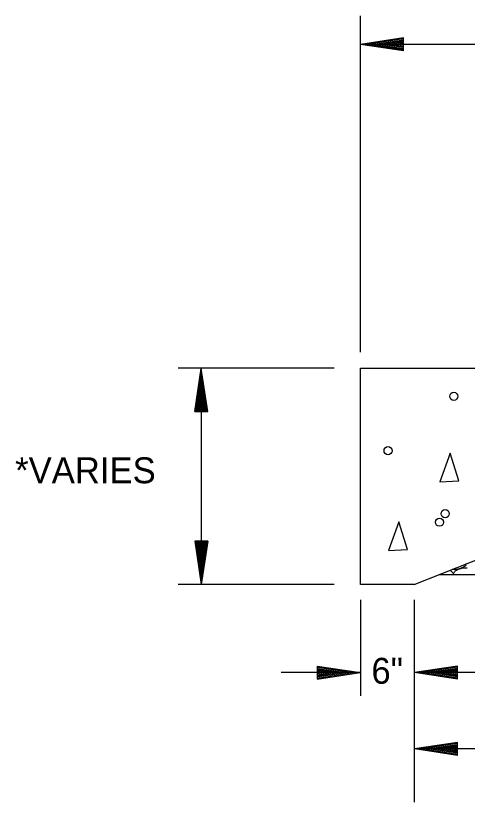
# Model space of a CAD drawing. Extents: x 1955771 to 1955918, y 566326 to 566544.
# Drawn here: x 1955782.9 to 1955793.36, y 566390.76 to 566408.95 of the extents above; entities that cross this region are included whole.
import ezdxf

# ---------------------------------------------------------------- set-up
doc = ezdxf.new("R2010")
doc.units = 0
doc.layers.add('Default', color=7, linetype='Continuous')

msp = doc.modelspace()

# ---------------------------------------------------------------- linework, layer by layer
at = {"layer": 'Default'}
for p, q in [((1955790.884, 566401.168), (1955790.884, 566408.948)), ((1955791.885, 566408.436), (1955790.885, 566408.286)), ((1955791.885, 566408.411), (1955791.052, 566408.286)), ((1955791.885, 566408.136), (1955791.885, 566408.436)), ((1955790.884, 566408.287), (1955840.88, 566408.287)), ((1955791.885, 566408.136), (1955790.885, 566408.286)), ((1955791.885, 566408.161), (1955791.052, 566408.286)), ((1955791.885, 566408.386), (1955791.222, 566408.286)), ((1955791.885, 566408.186), (1955791.222, 566408.286)), ((1955791.885, 566408.361), (1955791.39, 566408.286)), ((1955791.885, 566408.211), (1955791.39, 566408.286)), ((1955791.885, 566408.336), (1955791.56, 566408.286)), ((1955791.885, 566408.239), (1955791.56, 566408.286)), ((1955791.885, 566408.311), (1955791.727, 566408.286)), ((1955791.885, 566408.264), (1955791.727, 566408.286)), ((1955790.28, 566400.793), (1955786.667, 566400.793)), ((1955787.05, 566399.792), (1955787.2, 566400.792)), ((1955787.35, 566399.792), (1955787.2, 566400.792)), ((1955787.201, 566400.793), (1955787.201, 566395.793)), ((1955790.884, 566400.793), (1955882.128, 566400.793)), ((1955790.884, 566395.793), (1955790.884, 566400.793)), ((1955787.075, 566399.792), (1955787.2, 566400.627)), ((1955787.325, 566399.792), (1955787.2, 566400.627)), ((1955787.103, 566399.792), (1955787.2, 566400.454)), ((1955787.3, 566399.792), (1955787.2, 566400.454)), ((1955787.128, 566399.792), (1955787.2, 566400.287)), ((1955787.275, 566399.792), (1955787.2, 566400.287)), ((1955787.153, 566399.792), (1955787.2, 566400.117)), ((1955787.25, 566399.792), (1955787.2, 566400.117)), ((1955787.178, 566399.792), (1955787.2, 566399.952)), ((1955787.225, 566399.792), (1955787.2, 566399.952)), ((1955787.05, 566399.792), (1955787.35, 566399.792)), ((1955792.133, 566395.793), (1955797.133, 566397.772)), ((1955787.05, 566396.792), (1955787.2, 566395.792)), ((1955787.35, 566396.792), (1955787.05, 566396.792)), ((1955787.075, 566396.792), (1955787.2, 566395.959)), ((1955787.103, 566396.792), (1955787.2, 566396.132)), ((1955787.128, 566396.792), (1955787.2, 566396.299)), ((1955787.153, 566396.792), (1955787.2, 566396.467)), ((1955787.178, 566396.792), (1955787.2, 566396.634)), ((1955787.35, 566396.792), (1955787.2, 566395.792)), ((1955787.25, 566396.792), (1955787.2, 566396.467)), ((1955787.3, 566396.792), (1955787.2, 566396.132)), ((1955787.325, 566396.792), (1955787.2, 566395.959)), ((1955787.275, 566396.792), (1955787.2, 566396.299)), ((1955787.225, 566396.792), (1955787.2, 566396.634)), ((1955793.352, 566396.182), (1955793.36, 566396.182)), ((1955792.712, 566396.022), (1955837.131, 566396.022)), ((1955790.28, 566395.793), (1955786.667, 566395.793)), ((1955792.133, 566395.793), (1955790.884, 566395.793)), ((1955790.884, 566395.44), (1955790.884, 566393.221)), ((1955792.133, 566395.44), (1955792.133, 566390.756)), ((1955789.885, 566393.904), (1955790.885, 566393.754)), ((1955789.885, 566393.904), (1955789.885, 566393.604)), ((1955789.885, 566393.879), (1955790.717, 566393.754)), ((1955793.135, 566393.904), (1955792.135, 566393.754)), ((1955793.135, 566393.879), (1955792.302, 566393.754)), ((1955793.135, 566393.604), (1955793.135, 566393.904)), ((1955790.884, 566393.755), (1955789.048, 566393.755)), ((1955789.885, 566393.854), (1955790.545, 566393.754)), ((1955789.885, 566393.829), (1955790.38, 566393.754)), ((1955789.885, 566393.804), (1955790.21, 566393.754)), ((1955789.885, 566393.779), (1955790.043, 566393.754)), ((1955789.885, 566393.604), (1955790.885, 566393.754)), ((1955789.885, 566393.707), (1955790.21, 566393.754)), ((1955789.885, 566393.654), (1955790.545, 566393.754)), ((1955789.885, 566393.629), (1955790.717, 566393.754)), ((1955789.885, 566393.679), (1955790.38, 566393.754)), ((1955789.885, 566393.732), (1955790.043, 566393.754)), ((1955794.099, 566393.755), (1955792.133, 566393.755)), ((1955793.135, 566393.604), (1955792.135, 566393.754)), ((1955793.135, 566393.629), (1955792.302, 566393.754)), ((1955793.135, 566393.854), (1955792.472, 566393.754)), ((1955793.135, 566393.654), (1955792.472, 566393.754)), ((1955793.135, 566393.829), (1955792.64, 566393.754)), ((1955793.135, 566393.679), (1955792.64, 566393.754)), ((1955793.135, 566393.804), (1955792.81, 566393.754)), ((1955793.135, 566393.707), (1955792.81, 566393.754)), ((1955793.135, 566393.779), (1955792.977, 566393.754)), ((1955793.135, 566393.732), (1955792.977, 566393.754)), ((1955793.135, 566392.14), (1955792.135, 566391.99)), ((1955793.135, 566392.115), (1955792.302, 566391.99)), ((1955793.135, 566392.087), (1955792.472, 566391.99)), ((1955793.135, 566392.062), (1955792.64, 566391.99)), ((1955793.135, 566391.84), (1955793.135, 566392.14)), ((1955797.133, 566391.989), (1955792.133, 566391.989)), ((1955793.135, 566391.84), (1955792.135, 566391.99)), ((1955793.135, 566391.865), (1955792.302, 566391.99)), ((1955793.135, 566391.89), (1955792.472, 566391.99)), ((1955793.135, 566391.915), (1955792.64, 566391.99)), ((1955793.135, 566392.037), (1955792.81, 566391.99)), ((1955793.135, 566391.94), (1955792.81, 566391.99)), ((1955793.135, 566392.012), (1955792.977, 566391.99)), ((1955793.135, 566391.965), (1955792.977, 566391.99))]:
    msp.add_line(p, q, dxfattribs=at)
for points in [[(1955792.967, 566398.834), (1955792.725, 566398.169), (1955793.165, 566398.187), (1955792.967, 566398.834)], [(1955791.777, 566397.244), (1955791.535, 566396.579), (1955791.975, 566396.599), (1955791.777, 566397.244)]]:
    msp.add_lwpolyline(points, dxfattribs=at)
for centre in [(1955793.047, 566400.146), (1955791.525, 566398.888), (1955792.848, 566397.431), (1955792.716, 566397.233)]:
    msp.add_circle(centre, 0.0937, dxfattribs=at)
for points in [[(1955793.337, 566396.27), (1955793.31, 566396.227), (1955793.272, 566396.197), (1955793.195, 566396.162), (1955793.087, 566396.14), (1955793.032, 566396.14), (1955793.013, 566396.141)], [(1955792.963, 566396.122), (1955793.022, 566396.062), (1955793.032, 566396.025), (1955793.032, 566396.022)], [(1955793.04, 566396.022), (1955793.04, 566396.025), (1955793.06, 566396.085), (1955793.11, 566396.125), (1955793.16, 566396.147), (1955793.235, 566396.17), (1955793.282, 566396.18), (1955793.352, 566396.182)]]:
    msp.add_spline(points, degree=3, dxfattribs=at)

# ---------------------------------------------------------------- texts
for s, p in [('*VARIES', (1955782.89, 566398.135)), ('6"', (1955791.14, 566393.497))]:
    msp.add_text(s, height=0.6, dxfattribs=at).set_placement(p)

doc.saveas('drawing.dxf')
